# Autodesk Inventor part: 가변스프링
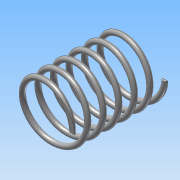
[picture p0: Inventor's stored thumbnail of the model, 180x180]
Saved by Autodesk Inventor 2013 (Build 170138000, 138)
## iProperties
Created: 2018-07
Part Number: 가변스프링
Material: 강철, 연강
Document SubType Name: Modeling
Designer: Administrator
Density: 7.86 g/cm^3
Mass: 83.1282 g
Surface Area: 106.475 cm^2
Volume: 10.5761 cm^3
Author: Administrator
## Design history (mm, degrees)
sketch "스케치1"
  geometry: L1 (0, 0)-(0, 73.25); L2 (0, 0)-(22.5, 0); L3 (0, 73.25)-(22.5, 73.25); C1 r 2 at (22.5, 0)
  constraints: 6 end point, 1 centre point, 1 horizontal alignment, 1 parallel, 1 perpendicular, 1 vertical
  dimensions: "d1" = 4 diameter of C1; "d2" = 45 diameter of L2.end L1; "d3" = 22.5 distance of L1.end L3.end; "d4" = 73.25 distance of L1.start L1.end (derived)
feature "코일1" sketch "스케치1" pitch "d5" = 10; turns "d7" = 6; dims "d6" = 73.25 (= d4), "d8" = 0, angle "d9" = 90 deg, angle "d10" = 90 deg, "d11" = 0, "d12" = 0
sketch "스케치3"
  geometry: L1 (73.25, 27.5)-(0, 27.5); L2 (0, 27.5)-(0, -27.5); L3 (0, -27.5)-(73.25, -27.5); L4 (73.25, -27.5)-(73.25, 27.5); 2 further points
  constraints: 8 end point, 2 parallel, 1 coincident, 1 horizontal, 1 midpoint, 1 perpendicular
  dimensions: "d13" = 55 distance of L3.end L1.start; "d15" = 73.25 distance of L1.start L1.end (derived)
extrude "돌출1" sketch "스케치3" stored distance "d16" = 10; taper "d17" = 0 deg
node "솔리드1"
